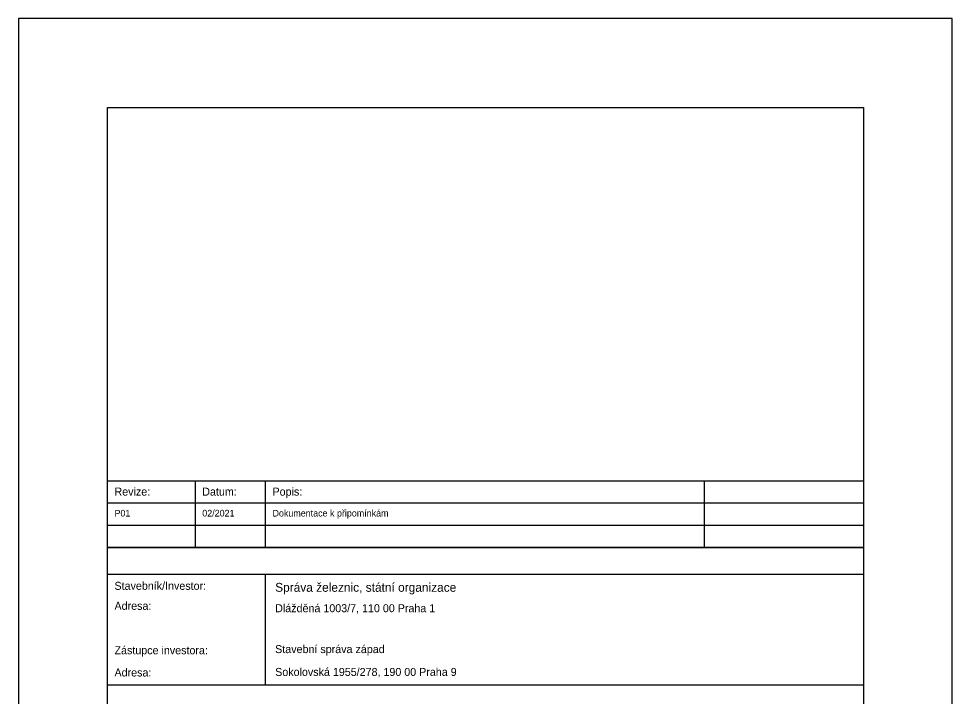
# Model space of a CAD drawing. Extents: x -729968 to -728918, y -1073811 to -1072326.
# Drawn here: x -729968 to -728918, y -1073089 to -1072326 of the extents above; entities that cross this region are included whole.
import ezdxf

# ---------------------------------------------------------------- set-up
doc = ezdxf.new("R2010")
doc.units = 0
for name, color, linetype in [('Rozpiska_pole_1', 7, 'Continuous'), ('Rozpiska_pole_4', 7, 'Continuous'), ('Rozpiska_pole_5', 7, 'Continuous'), ('Rozpiska_pole_6', 7, 'Continuous')]:
    doc.layers.add(name, color=color, linetype=linetype)

msp = doc.modelspace()

# ---------------------------------------------------------------- linework, layer by layer
msp.add_lwpolyline([(-729968.3, -1073811.1), (-728918.3, -1073811.1), (-728918.3, -1072326.1), (-729968.3, -1072326.1)], close=True)
at = {"layer": 'Rozpiska_pole_1'}
msp.add_lwpolyline([(-729868.3, -1072426.1), (-729018.3, -1072426.1), (-729018.3, -1073726.1), (-729868.3, -1073726.1)], close=True, dxfattribs=at)
at = {"layer": 'Rozpiska_pole_4'}
for p, q in [((-729769.5, -1072921.1), (-729769.5, -1072846.1)), ((-729690.5, -1072921.1), (-729690.5, -1072846.1)), ((-729196.8, -1072921.1), (-729196.8, -1072846.1)), ((-729868.3, -1072871.1), (-729018.3, -1072871.1)), ((-729868.3, -1072896.1), (-729018.3, -1072896.1)), ((-729868.3, -1072921.1), (-729018.3, -1072921.1))]:
    msp.add_line(p, q, dxfattribs=at)
msp.add_lwpolyline([(-729868.3, -1072846.1), (-729018.3, -1072846.1), (-729018.3, -1072921.1), (-729868.3, -1072921.1)], close=True, dxfattribs=at)
at = {"layer": 'Rozpiska_pole_5'}
msp.add_line((-729690.5, -1073076.1), (-729690.5, -1072951.1), dxfattribs=at)
msp.add_lwpolyline([(-729868.3, -1072951.1), (-729018.3, -1072951.1), (-729018.3, -1073076.1), (-729868.3, -1073076.1)], close=True, dxfattribs=at)

# ---------------------------------------------------------------- texts
at = {"layer": 'Rozpiska_pole_4'}
for s, height, p in [('Revize:', 9, (-729860.5, -1072862.8)), ('Datum:', 9, (-729761.8, -1072862.8)), ('Popis:', 9, (-729682.8, -1072862.8)), ('P01', 7.5, (-729860.5, -1072886.3)), ('02/2021', 7.5, (-729761.8, -1072886.3)), ('Dokumentace k připomínkám', 7.5, (-729682.8, -1072886.3))]:
    msp.add_text(s, height=height, dxfattribs=at).set_placement(p)
at = {"layer": 'Rozpiska_pole_5'}
for s, height, p in [('Stavebník/Investor:', 9, (-729860.5, -1072968.8)), ('Správa železnic, státní organizace', 10, (-729679.8, -1072971)), ('Adresa:', 9, (-729860.5, -1072991.3)), ('Zástupce investora:', 9, (-729860.5, -1073041.3)), ('Adresa:', 9, (-729860.5, -1073066.3))]:
    msp.add_text(s, height=height, dxfattribs=at).set_placement(p)
at = {"layer": 'Rozpiska_pole_6'}
for s, p in [('Dlážděná 1003/7, 110 00 Praha 1', (-729679.8, -1072994)), ('Stavební správa západ', (-729679.8, -1073040)), ('Sokolovská 1955/278, 190 00 Praha 9', (-729679.8, -1073065.7))]:
    msp.add_text(s, height=9, dxfattribs=at).set_placement(p)

doc.saveas('drawing.dxf')
